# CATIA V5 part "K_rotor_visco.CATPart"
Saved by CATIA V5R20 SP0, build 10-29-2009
Part number: rotor visco
Bounding box of the stored display mesh (mm): x -90 to 90, y -345 to -85, z -90 to 90
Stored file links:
  G:\Khaled_CFAO_2011\ST2M\ST2M_GR1\mponsin\Khaled\CAD_ThinkMOTION\K_rotor_visco.CATPart
  C:\Users\Socar\Documents\thinkmotion\Final\Diff2.CATProduct
  G:\Khaled_CFAO_2011\ST2M\ST2M_GR1\mponsin\Khaled\CAD_ThinkMOTION\K_mponsin.CATProduct
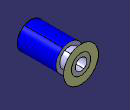
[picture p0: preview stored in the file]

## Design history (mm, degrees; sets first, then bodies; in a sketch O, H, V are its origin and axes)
Parameters
  `Rint disques visco` = 70 mm
External parameters (linked from other documents)
  `External.R interface stat_tot` = 50 mm
  `External.R cardan` = 30 mm
Set1
  Plane1 "stator_rotor1": linked copy from another document
  Plane2 "stator_rotor2": linked copy from another document
  Plane3 "stator_rotor3": linked copy from another document
  Line1 "axe general": linked copy from another document
  DatumSurface1: linked copy from another document
Body1 (main body)
  Sketch1 on yz-plane, origin (0, 0, 0), H (0, 1, 0), V (0, 0, 1)
    line L1 (-345, 70) -> (-145, 70)
    line L2 (-145, 70) -> (-145, 50)
    line L3 (-242, 50) -> (-345, 50)
    line L4 (-345, 50) -> (-345, 70)
    line L5 (-145, 50) -> (-85, 50)
    line L6 (-85, 50) -> (-85, 30)
    line L7 (-85, 30) -> (-242, 30)
    line L8 (-242, 30) -> (-242, 50)
    reference intersected line E1 through (-345, 0) direction (0, 1) from Plane1
    reference intersected line E2 through (-245, 0) direction (0, 1) from Plane2
    reference intersected line E3 through (-145, 0) direction (0, 1) from Plane3
    reference intersected line E4 through (-85, 0) direction (0, -1) from face of DatumSurface1
    distance H L7 = 30 {= `External.R cardan`}
    distance L5 H = 50 {= `External.R interface stat_tot`}
    distance L8 E2 = 3
    distance L1 H = 70 {= `Rint disques visco`}
    horizontal: L1 H, L3 H, L5 H, L7 H
    vertical: L2 V, L4 V, L6 V, L8 V
    coincidence: L3 L5, E1 L4, E3 L2, E4 L6
  Shaft1: profile Sketch1, axis Line1, angle 360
